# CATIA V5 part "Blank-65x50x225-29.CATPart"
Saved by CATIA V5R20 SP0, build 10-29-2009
Part number: BalsaBlock-65x50x225x29
Material "Balsa": density 139 kg/m3
Bounding box of the stored display mesh (mm): x -2.9 to 227.9, y -31.9 to 23.9, z -32.5 to 32.5
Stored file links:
  C:\Users\brett.REA-SERVER\Documents\REA\Car Parts\Blank-65x50x225-29.CATPart
  F:\New Folder\Impulse Racing\Impulse Cars\CATMaterial1.CATMaterial
  C:\Documents and Settings\nathan\Desktop\20_SEAT_CATIA_Fundamentals_Trg_Package\09_SEAT_Trg_Cse_V5R16_Data\REA Training Data\balsa_smallest.jpg
  H:\REA Training Draft 1104\02_REA Training Data\01_CATIAParts&Products\V5R12+\REA-SampleMachiningAssembly-01.CATProduct
  C:\_CustomerRelatedData\cust_REA\Rochelle\UK TRIP\Daniel Total package\FinalCar-Mk5.CATPart
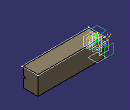
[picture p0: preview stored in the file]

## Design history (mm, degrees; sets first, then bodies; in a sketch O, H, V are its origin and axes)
Set1
  Plane1 "SIDE MACHINING SAFETY PLANE": type Offset, RefPlane xy-plane, Offset 40
  Plane2 "SIDE MACHINING - BOTTOM PLANE": type Offset, RefPlane xy-plane, Offset 5, reversed
  Sketch1 "Limiting Contour for Z leveling" on face of Pad1 from Sketch2.L6, origin (0, 0, 32.5), H (1, 0, 0), V (0, 1, 0)
  Plane3 "TOP MACHINING - SAFETY PLANE": type Offset, RefPlane zx-plane, Offset 40
  Plane4 "TOP MACHINING- BOTTOM PLANE": type Offset, RefPlane zx-plane, Offset 19, reversed
  Plane5: type Offset, RefPlane xy-plane, Offset 40, reversed
  Plane6: type Offset, RefPlane xy-plane, Offset 5
  Plane7: type Offset, RefPlane zx-plane, Offset 30, reversed
  Plane8: type Offset, RefPlane zx-plane, Offset 12, reversed
  Plane9: type Offset, RefPlane Plane4, Offset 2, reversed
  Plane10: type Offset, RefPlane Plane3, Offset 18, reversed
Body1 (main body)
  Sketch2 on yz-plane, origin (0, 0, 0), H (0, 1, 0), V (0, 0, 1)
    line L1 (-29, -32.5) -> (-29, -3)
    line L2 (-29, -3) -> (-23, -3)
    line L3 (-23, -3) -> (-23, 3)
    line L4 (-23, 3) -> (-29, 3)
    line L5 (-29, 3) -> (-29, 32.5)
    line L6 (-29, 32.5) -> (21, 32.5)
    line L7 (21, 32.5) -> (21, -32.5)
    line L8 (21, -32.5) -> (-29, -32.5)
    length L7 = 65
    length L6 = 50
    length L3 = 6
    length L4 = 6
    angle H L5 = 90
    angle L4 V = 270
    angle V L8 = 90
    coincidence: L1 L5
  Pad1: profile Sketch2, direction (1, 0, 0), length 225
  Sketch3 on face of Pad1, origin (0, -20.589, -0.7656), H (0, 1, 0), V (0, 0, -1)
    point P1 (20.589, -0.7656)
    reference intersected line E1 through (0, -0.7656) direction (1, 0) from xy-plane
    reference projected line E2 (-8.411, -33.2656) -> (-8.411, -3.7656) from edge [start face of Pad1 | face of Pad1 from Sketch2.L5]
    distance P1 E2 = 29
    coincidence: P1 E1
  Hole1: placed by Sketch3, at (0, 0, 0) direction (1, 0, 0), diameter 19, depth 52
